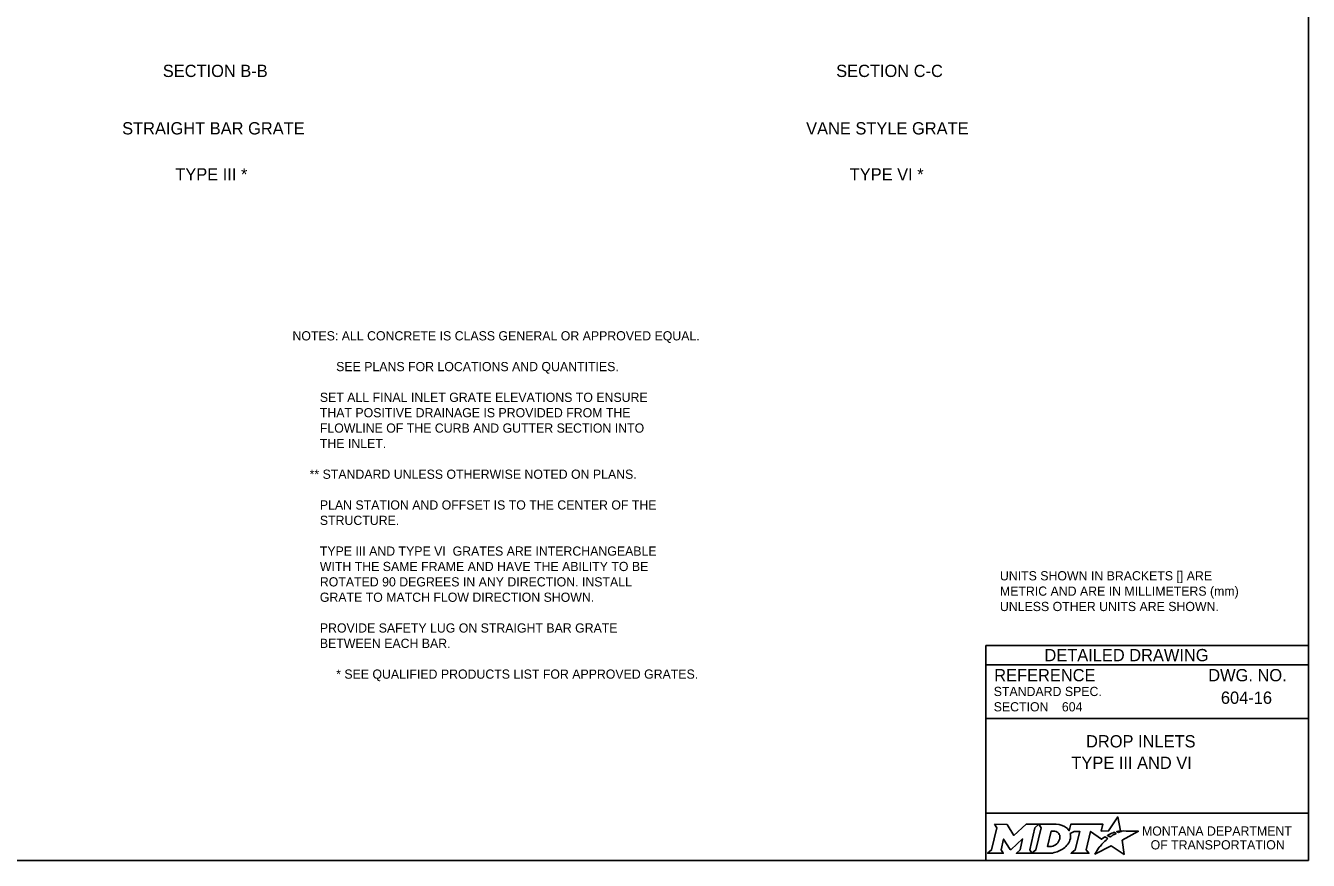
# Model space of a CAD drawing. Extents: x 49991.4 to 50041.6, y 49987.6 to 50011.4.
# Drawn here: x 50008.39 to 50016.75, y 49987.8 to 49993.24 of the extents above; entities that cross this region are included whole.
import ezdxf

# ---------------------------------------------------------------- set-up
doc = ezdxf.new("R2010")
doc.units = 0
for name, color, linetype in [('Default', 7, 'Continuous'), ('Level 1', 7, 'Continuous'), ('Level 2', 7, 'Continuous'), ('Level 5', 7, 'Continuous')]:
    doc.layers.add(name, color=color, linetype=linetype)

msp = doc.modelspace()

# ---------------------------------------------------------------- linework, layer by layer
at = {"layer": 'Default'}
for points in [[(50014.7056, 49988.0338), (50014.7197, 49988.0104), (50014.6862, 49987.8671), (50014.6605, 49987.8446), (50014.7621, 49987.8446), (50014.7486, 49987.8674), (50014.7648, 49987.9375), (50014.8085, 49987.8685), (50014.8138, 49987.8685), (50014.8889, 49987.938), (50014.8725, 49987.8669), (50014.8478, 49987.8449), (50014.9494, 49987.8449), (50014.9356, 49987.8682), (50014.9688, 49988.0106)], [(50014.9688, 49988.0106), (50014.9941, 49988.0338), (50014.9117, 49988.0338), (50014.8321, 49987.9608), (50014.7876, 49988.0335), (50014.7056, 49988.0338)], [(50015.1077, 49988.0338), (50014.9941, 49988.0338), (50015.0088, 49988.0109), (50014.9749, 49987.8671), (50014.9494, 49987.8449), (50015.06, 49987.8449)], [(50015.5126, 49987.9811), (50015.5023, 49987.9867), (50015.5139, 49987.9895), (50015.5255, 49987.9915), (50015.5081, 49988.0816), (50015.4486, 49987.9903), (50015.4013, 49987.9896), (50015.4116, 49988.0337), (50015.2024, 49988.0338), (50015.1923, 49987.9913), (50015.1865, 49987.9996)], [(50015.1317, 49987.9471), (50015.1305, 49987.939), (50015.1273, 49987.9297), (50015.1231, 49987.9215), (50015.1175, 49987.914), (50015.111, 49987.9071), (50015.1031, 49987.9008), (50015.0948, 49987.8961), (50015.0857, 49987.8922), (50015.0766, 49987.8899), (50015.0674, 49987.889), (50015.0515, 49987.889), (50015.0751, 49987.989), (50015.0911, 49987.989), (50015.0987, 49987.9884), (50015.1063, 49987.9865), (50015.1129, 49987.9835), (50015.119, 49987.9793), (50015.1238, 49987.9743), (50015.1275, 49987.9683), (50015.1302, 49987.9621), (50015.1318, 49987.9547), (50015.1318, 49987.9517), (50015.1317, 49987.9471)], [(50015.1991, 49987.9747), (50015.2237, 49987.9878), (50015.2606, 49987.9878), (50015.232, 49987.8673), (50015.2045, 49987.8446), (50015.3207, 49987.8446), (50015.3037, 49987.8675), (50015.3319, 49987.9877), (50015.4032, 49987.936), (50015.4243, 49987.9511), (50015.444, 49987.9402)], [(50015.3882, 49987.8843), (50015.3729, 49987.8599), (50015.3682, 49987.8524), (50015.3624, 49987.8438), (50015.3601, 49987.8395), (50015.4654, 49987.8926), (50015.5493, 49987.8375), (50015.5362, 49987.9302), (50015.6431, 49987.9886), (50015.5938, 49987.9894), (50015.5637, 49987.9898), (50015.5429, 49987.9901), (50015.5361, 49987.9886), (50015.5312, 49987.9874), (50015.5228, 49987.9851), (50015.5126, 49987.9811)], [(50015.4622, 49987.9535), (50015.4598, 49987.9518), (50015.4415, 49987.9614), (50015.4518, 49987.9671), (50015.4559, 49987.9693), (50015.4645, 49987.9733), (50015.4702, 49987.9759), (50015.4781, 49987.9789), (50015.4854, 49987.9816), (50015.4972, 49987.9742), (50015.4932, 49987.9721), (50015.4886, 49987.9696), (50015.4844, 49987.9674), (50015.4794, 49987.9645), (50015.4775, 49987.9634), (50015.4748, 49987.9618), (50015.4723, 49987.9604), (50015.47, 49987.9588), (50015.4674, 49987.957), (50015.4647, 49987.9552), (50015.4622, 49987.9535)], [(50015.1057, 49987.8522), (50015.1141, 49987.8548), (50015.1271, 49987.8602), (50015.1475, 49987.8712)], [(50015.4021, 49987.9004), (50015.4021, 49987.9004)]]:
    msp.add_lwpolyline(points, dxfattribs=at)
for centre, radius, start, end in [((50015.0868, 49987.9727), 0.1183, 300.91025, 339.13831), ((50015.1308, 49987.9554), 0.0709, 339.53292, 15.85821)]:
    msp.add_arc(centre, radius, start, end, dxfattribs=at)
for centre, major_axis, ratio, start_param, end_param in [((50015.1056, 49987.9864), (0.0834, -0.0037), 0.568097, 0.61298, 1.570796), ((50015.1612, 49987.9937), (0.0361, -0.0295), 0.469099, 1.225588, 1.570796), ((50015.4329, 49987.9305), (-0.0112, -0.0097), 0.021651, 3.157348, 6.283185), ((50015.0603, 49987.9932), (0, 0.1484), 0.987302, 3.139398, 3.456847), ((50015.3952, 49987.8923), (-0.00694, -0.00806), 0.008222, 0, 3.137361), ((50015.4119, 49987.9106), (-0.0098, -0.0102), 0.016458, 3.141593, 6.279097)]:
    msp.add_ellipse(centre, major_axis=major_axis, ratio=ratio, start_param=start_param, end_param=end_param, dxfattribs=at)
at = {"layer": 'Level 1'}
msp.add_line((50009.6794, 49992.9432), (50009.6794, 49992.9432), dxfattribs=at)
msp.add_lwpolyline([(49999.3835, 49998.9992), (50016.7501, 49998.9992), (50016.7501, 49987.7988), (49999.3835, 49987.7988)], close=True, dxfattribs=at)
at = {"layer": 'Level 5'}
for p, q in [((50016.7501, 49989.1988), (50014.6501, 49989.1988)), ((50014.6501, 49989.1988), (50014.6501, 49987.7988)), ((50016.7501, 49989.0738), (50014.6501, 49989.0738)), ((50016.3862, 49988.8587), (50016.3862, 49988.8587)), ((50015.1444, 49988.7993), (50015.1444, 49988.7993)), ((50016.7501, 49988.7238), (50014.6501, 49988.7238)), ((50015.7001, 49988.4747), (50015.7001, 49988.4747)), ((50016.7501, 49988.1057), (50014.6501, 49988.1057))]:
    msp.add_line(p, q, dxfattribs=at)

# ---------------------------------------------------------------- texts
at = {"layer": 'Default'}
for s, p in [('MONTANA DEPARTMENT', (50015.6663, 49987.96)), ('OF TRANSPORTATION', (50015.7225, 49987.87))]:
    msp.add_text(s, height=0.06, dxfattribs=at).set_placement(p)
at = {"layer": 'Level 2'}
for s, height, p in [('SECTION B-B', 0.08, (50009.2873, 49992.9032)), ('SECTION C-C', 0.08, (50013.674, 49992.9032)), ('STRAIGHT BAR GRATE', 0.08, (50009.0227, 49992.5289)), ('VANE STYLE GRATE', 0.08, (50013.4784, 49992.5289)), ('TYPE III *', 0.08, (50009.3688, 49992.2289)), ('TYPE VI *', 0.08, (50013.7623, 49992.2289)), ('NOTES: ALL CONCRETE IS CLASS GENERAL OR APPROVED EQUAL.', 0.06, (50010.1322, 49991.1868)), ('  SEE PLANS FOR LOCATIONS AND QUANTITIES.', 0.06, (50010.3722, 49990.9864)), ('        SET ALL FINAL INLET GRATE ELEVATIONS TO ENSURE', 0.06, (50010.1322, 49990.786)), ('        THAT POSITIVE DRAINAGE IS PROVIDED FROM THE ', 0.06, (50010.1322, 49990.6858)), ('        FLOWLINE OF THE CURB AND GUTTER SECTION INTO', 0.06, (50010.1322, 49990.5856)), ('        THE INLET.', 0.06, (50010.1322, 49990.4854)), ('     ** STANDARD UNLESS OTHERWISE NOTED ON PLANS.', 0.06, (50010.1322, 49990.285)), ('        PLAN STATION AND OFFSET IS TO THE CENTER OF THE', 0.06, (50010.1322, 49990.0846)), ('        STRUCTURE.', 0.06, (50010.1322, 49989.9844)), ('        TYPE III AND TYPE VI  GRATES ARE INTERCHANGEABLE', 0.06, (50010.1322, 49989.784)), ('        WITH THE SAME FRAME AND HAVE THE ABILITY TO BE', 0.06, (50010.1322, 49989.6838)), ('UNITS SHOWN IN BRACKETS [] ARE ', 0.06, (50014.7408, 49989.6231)), ('        ROTATED 90 DEGREES IN ANY DIRECTION. INSTALL', 0.06, (50010.1322, 49989.5836)), ('        GRATE TO MATCH FLOW DIRECTION SHOWN.', 0.06, (50010.1322, 49989.4834)), ('METRIC AND ARE IN MILLIMETERS (mm) ', 0.06, (50014.7408, 49989.5231)), ('UNLESS OTHER UNITS ARE SHOWN.', 0.06, (50014.7408, 49989.4231)), ('        PROVIDE SAFETY LUG ON STRAIGHT BAR GRATE ', 0.06, (50010.1322, 49989.283)), ('        BETWEEN EACH BAR.', 0.06, (50010.1322, 49989.1828)), ('  * SEE QUALIFIED PRODUCTS LIST FOR APPROVED GRATES.', 0.06, (50010.3722, 49988.9824)), ('604-16', 0.08, (50016.1804, 49988.8187)), ('604', 0.06, (50015.1444, 49988.7693)), ('DROP INLETS', 0.08, (50015.3018, 49988.5347)), ('TYPE III AND VI', 0.08, (50015.2063, 49988.3947))]:
    msp.add_text(s, height=height, dxfattribs=at).set_placement(p)
at = {"layer": 'Level 5'}
for s, height, p in [('DETAILED DRAWING', 0.0799, (50015.0311, 49989.0963)), ('REFERENCE', 0.08, (50014.7037, 49988.9654)), ('DWG. NO.', 0.08, (50016.0979, 49988.9654)), ('STANDARD SPEC.', 0.06, (50014.7004, 49988.8694)), ('SECTION', 0.06, (50014.7004, 49988.7694))]:
    msp.add_text(s, height=height, dxfattribs=at).set_placement(p)

doc.saveas('drawing.dxf')
